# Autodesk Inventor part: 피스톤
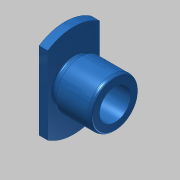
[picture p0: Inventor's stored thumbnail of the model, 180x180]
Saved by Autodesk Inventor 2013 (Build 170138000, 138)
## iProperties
Created: 2019-02
Part Number: 피스톤
Material: 알루미늄 6061
Document SubType Name: Modeling
Designer: mduedu
Density: 1 g/cm^3
Author: mduedu
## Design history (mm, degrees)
sketch "스케치1"
  geometry: C1 r 27 at (0, 0); 1 further point
  constraints: 1 centre point, 1 coincident
  dimensions: "d0" = 54 diameter of C1
extrude "돌출1" new body sketch "스케치1" distance "d1" = 5; taper "d2" = 0 deg
sketch "스케치2"
  geometry: L1 (-15, -27)-(15, -27); L2 (15, -27)-(15, 27); L3 (15, 27)-(-15, 27); L4 (-15, 27)-(-15, -27); L5 (-15, -27)-(15, 27); L6 (15, -27)-(-15, 27); C1 r 27 at (0, 0) reference; 1 further point
  constraints: 12 end point, 2 midpoint, 2 parallel, 1 horizontal, 1 perpendicular, 1 tangent
  dimensions: "d3" = 30 distance of L2.end L3.end
extrude "돌출2" sketch "스케치2" stored distance "d5" = 5; taper "d6" = 0 deg
sketch "스케치3"
  geometry: C1 r 12 at (0, 0); 1 further point
  constraints: 1 centre point, 1 coincident
  dimensions: "d7" = 24 diameter of C1
extrude "돌출3" join sketch "스케치3" distance "d8" = 4; taper "d9" = 0 deg
sketch "스케치4"
  geometry: C1 r 14 at (0, 0); 1 further point
  constraints: 1 centre point, 1 coincident
  dimensions: "d10" = 28 diameter of C1
extrude "돌출4" join sketch "스케치4" distance "d11" = 20; taper "d12" = 0 deg
fillet "모깎기1" dims "d13" = 1
chamfer "모따기1" distance "d14" = 1.8; stored, may be unused: second distance "d15" = 2, angle "d16" = 15 deg
fillet "모깎기2" dims "d17" = 1, "d18" = 2
sketch "스케치5"
  geometry: 2 further points
  constraints: 1 coincident
hole "구멍1" sketch "스케치5" at (0, 0) diameter "d19" = 18; stored, may be unused: countersink angle "d23" = 90 deg, drill point angle "d25" = 118 deg; dims "d20" = 6, "d21" = 4, "d22" = 2, "d24" = 15
node "솔리드1"
